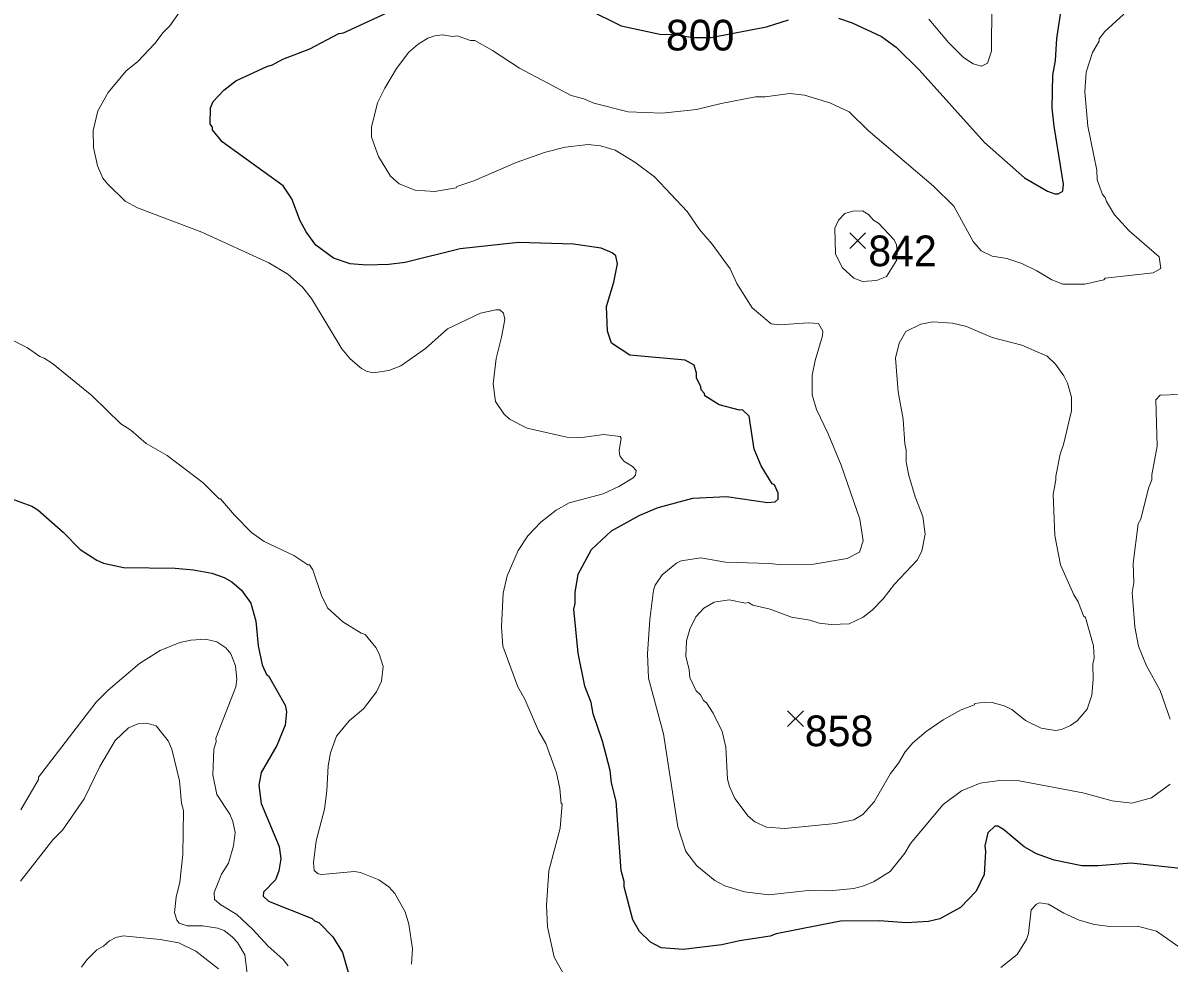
# Model space of a CAD drawing. Extents: x 265.7 to 292.1, y 7676.2 to 7704.2.
# Drawn here: x 270.421 to 273.408, y 7689.995 to 7692.446 of the extents above; entities that cross this region are included whole.
import ezdxf
from ezdxf.enums import TextEntityAlignment as Align

# ---------------------------------------------------------------- set-up
doc = ezdxf.new("R2010")
doc.units = 0
doc.header["$LTSCALE"] = 0.032
for name, color, linetype, lineweight in [('1', 7, 'Continuous', 25), ('2', 7, 'Continuous', 13), ('21', 7, 'Continuous', 25)]:
    doc.layers.add(name, color=color, linetype=linetype, lineweight=lineweight)
doc.layers.add('61', color=7, linetype='Continuous')

msp = doc.modelspace()

# ---------------------------------------------------------------- linework, layer by layer
at = {"layer": '1'}
for points in [[(271.4171, 7691.8211), (271.374, 7691.8163), (271.3166, 7691.8147), (271.2735, 7691.8179), (271.2304, 7691.8323), (271.1841, 7691.8666), (271.1586, 7691.9009), (271.1434, 7691.9296), (271.1219, 7691.9871), (271.0987, 7692.0214), (270.9399, 7692.1355), (270.9144, 7692.1674), (270.9144, 7692.1738), (270.9088, 7692.1818), (270.9096, 7692.2249), (270.9168, 7692.2409), (270.9439, 7692.2704), (270.9758, 7692.2951), (271.0564, 7692.3326), (271.0708, 7692.3366), (271.0979, 7692.3518), (271.1682, 7692.3781), (271.244, 7692.418), (271.2559, 7692.4204), (271.4123, 7692.4922)], [(271.8927, 7692.4818), (271.9805, 7692.4387), (272.081, 7692.4164), (272.1199, 7692.4156), (272.1671, 7692.4081), (272.2142, 7692.4081), (272.3587, 7692.4355), (272.4162, 7692.4539)], [(272.547, 7692.4587), (272.5821, 7692.4459), (272.6587, 7692.4108), (272.697, 7692.3829), (272.7569, 7692.3238), (272.9276, 7692.1339), (273.0314, 7692.0422), (273.0912, 7692.007), (273.1104, 7691.9999), (273.1192, 7691.9999), (273.1311, 7692.007), (273.1335, 7692.0254), (273.1088, 7692.177), (273.104, 7692.2233), (273.1056, 7692.3095), (273.112, 7692.3478), (273.116, 7692.4052), (273.1295, 7692.4962)], [(271.9661, 7691.8387), (271.9565, 7691.8467), (271.9278, 7691.8586), (271.856, 7691.869), (271.7124, 7691.8738), (271.5608, 7691.857), (271.4171, 7691.8211)], [(273.4535, 7690.2395), (273.3099, 7690.2555), (273.2237, 7690.2483), (273.1806, 7690.2483), (273.1088, 7690.2627), (273.0625, 7690.2794), (273.0306, 7690.2978), (272.9771, 7690.3433), (272.962, 7690.3513), (272.954, 7690.3513), (272.9356, 7690.3345), (272.9284, 7690.3002), (272.93, 7690.2858), (272.926, 7690.2252), (272.9053, 7690.1821), (272.8646, 7690.1398), (272.8104, 7690.1103), (272.7816, 7690.1031), (272.7242, 7690.0999), (272.6524, 7690.1047), (272.5518, 7690.1039), (272.3842, 7690.0712), (272.3683, 7690.0648), (272.2885, 7690.0528), (272.2422, 7690.0425), (272.1417, 7690.0297), (272.0842, 7690.0345), (272.0563, 7690.0488), (272.0283, 7690.0768), (272.0108, 7690.1071), (271.9877, 7690.1933), (271.9877, 7690.2076), (271.9805, 7690.2364), (271.9669, 7690.4167), (271.9549, 7690.4646), (271.9517, 7690.4965), (271.931, 7690.5731), (271.9071, 7690.6449), (271.9015, 7690.6737), (271.8855, 7690.7167), (271.868, 7690.8029), (271.8568, 7690.9178), (271.86, 7690.9322), (271.86, 7690.9609), (271.868, 7691.0088), (271.9031, 7691.0726), (271.9549, 7691.1213), (272.0284, 7691.1628), (272.0762, 7691.1827), (272.1672, 7691.2067), (272.255, 7691.2107), (272.3619, 7691.1955), (272.3819, 7691.1971), (272.3898, 7691.2043), (272.389, 7691.2195), (272.3794, 7691.2418), (272.3739, 7691.2442), (272.3451, 7691.2913), (272.3268, 7691.3344), (272.314, 7691.4205), (272.2965, 7691.4373), (272.2885, 7691.4365), (272.2358, 7691.4501), (272.1983, 7691.4732), (272.1975, 7691.4796), (272.1887, 7691.4892), (272.1879, 7691.4971), (272.1768, 7691.5203), (272.1768, 7691.5323), (272.1704, 7691.5538), (272.1465, 7691.5666), (272.0028, 7691.5793), (271.9549, 7691.6113), (271.9446, 7691.6424), (271.9422, 7691.7062), (271.9613, 7691.7701), (271.9701, 7691.8179), (271.9661, 7691.8387)], [(270.3957, 7691.2035), (270.4436, 7691.1859), (270.4596, 7691.1764), (270.5258, 7691.1181), (270.5697, 7691.0726), (270.6128, 7691.0447), (270.6303, 7691.0375), (270.683, 7691.0263), (270.8171, 7691.0247), (270.8649, 7691.02), (270.9128, 7691.0112), (270.9447, 7691), (270.9655, 7690.9888), (270.9902, 7690.9673), (271.0149, 7690.933), (271.0277, 7690.8859), (271.0341, 7690.8221), (271.0445, 7690.7726), (271.0556, 7690.7471), (271.0604, 7690.7439), (271.1043, 7690.6673), (271.1075, 7690.6497), (271.1043, 7690.6146), (271.082, 7690.5619), (271.0413, 7690.4917), (271.0357, 7690.4582), (271.0413, 7690.4103), (271.0883, 7690.2986), (271.0931, 7690.2667), (271.0875, 7690.2348), (271.0788, 7690.2116), (271.0476, 7690.1797), (271.0469, 7690.1693), (271.0604, 7690.1558), (271.1745, 7690.1111), (271.1809, 7690.1047), (271.1921, 7690.1007), (271.228, 7690.0632), (271.2535, 7690.0225), (271.2791, 7689.9347)]]:
    msp.add_lwpolyline(points, dxfattribs=at)
at = {"layer": '2'}
for points in [[(270.841, 7692.4914), (270.8035, 7692.4387), (270.7859, 7692.4212), (270.7644, 7692.3925), (270.7189, 7692.3446), (270.6894, 7692.3206), (270.6431, 7692.2648), (270.616, 7692.2169), (270.604, 7692.1658), (270.6048, 7692.1212), (270.6152, 7692.0733), (270.6287, 7692.0414), (270.6407, 7692.0262), (270.687, 7691.9815), (270.7189, 7691.964), (270.8873, 7691.9001), (271.0612, 7691.8203), (271.1115, 7691.7908), (271.149, 7691.7565), (271.1729, 7691.727), (271.2519, 7691.5961), (271.2735, 7691.5698), (271.303, 7691.545), (271.3182, 7691.537), (271.3341, 7691.5338), (271.374, 7691.5394), (271.4059, 7691.5522), (271.4698, 7691.5969), (271.5272, 7691.648), (271.6134, 7691.6895), (271.6533, 7691.6982), (271.6637, 7691.6974), (271.6733, 7691.6887), (271.6765, 7691.6727), (271.6685, 7691.6264), (271.6541, 7691.5706), (271.6461, 7691.5051), (271.6525, 7691.4588), (271.6741, 7691.4269), (271.6892, 7691.4126), (271.7347, 7691.3894), (271.8384, 7691.3655), (271.8783, 7691.3647), (271.9342, 7691.3727), (271.9773, 7691.3679), (271.9797, 7691.3631), (271.9749, 7691.3312), (271.9765, 7691.3168), (271.9869, 7691.3032), (272.0092, 7691.2897)], [(272.9468, 7692.493), (272.9452, 7692.3725), (272.9348, 7692.3406), (272.9197, 7692.3334), (272.8973, 7692.339), (272.8726, 7692.3558), (272.8343, 7692.3941), (272.7824, 7692.4555)], [(273.2907, 7692.4691), (273.2413, 7692.4236), (273.2261, 7692.4044), (273.2261, 7692.398), (273.2085, 7692.3685), (273.1926, 7692.3175), (273.1886, 7692.2664), (273.1966, 7692.177), (273.2197, 7692.0621), (273.2213, 7692.0366)], [(273.3825, 7691.8363), (273.3873, 7691.806), (273.3673, 7691.794), (273.2421, 7691.7804), (273.2381, 7691.7764), (273.1886, 7691.7645), (273.1311, 7691.7645), (273.1024, 7691.7764), (273.0641, 7691.7996), (273.0242, 7691.8187), (272.9859, 7691.8315), (272.9476, 7691.8379), (272.9189, 7691.8514), (272.8973, 7691.8762), (272.8471, 7691.9679), (272.7944, 7692.0206), (272.6236, 7692.1658), (272.5742, 7692.2137), (272.5239, 7692.2377), (272.4577, 7692.2576), (272.4194, 7692.2616), (272.3555, 7692.2528), (272.33, 7692.2528), (272.2406, 7692.2361), (272.1768, 7692.2201), (272.0874, 7692.2105), (271.998, 7692.2137), (271.9087, 7692.2369), (271.8831, 7692.248), (271.8496, 7692.2568), (271.7148, 7692.3278), (271.6445, 7692.3741), (271.5983, 7692.4004), (271.5871, 7692.4004), (271.5528, 7692.4124), (271.54, 7692.4108), (271.5145, 7692.4148), (271.4945, 7692.4124), (271.4762, 7692.406), (271.4506, 7692.3909), (271.4267, 7692.3693), (271.3948, 7692.327), (271.3636, 7692.276), (271.3445, 7692.2377), (271.3293, 7692.1738), (271.3293, 7692.1483), (271.3477, 7692.0972), (271.3788, 7692.0461), (271.4012, 7692.0262), (271.4427, 7692.0102), (271.4937, 7692.0062), (271.5496, 7692.0158), (271.552, 7692.019), (271.5959, 7692.0342), (271.706, 7692.0821), (271.7826, 7692.1092), (271.8337, 7692.1219), (271.8943, 7692.1291), (271.9262, 7692.1251), (271.9645, 7692.114), (272.0156, 7692.0828), (272.0667, 7692.0445), (272.152, 7691.9544), (272.1847, 7691.9073), (272.2175, 7691.869), (272.2646, 7691.8044), (272.2813, 7691.7669), (272.3212, 7691.703), (272.3715, 7691.6615), (272.3922, 7691.6591), (272.4688, 7691.6639), (272.4944, 7691.6623), (272.5055, 7691.6424), (272.5047, 7691.6296), (272.4856, 7691.5658), (272.4776, 7691.5275), (272.4776, 7691.4764), (272.4896, 7691.4381), (272.5199, 7691.3743), (272.5534, 7691.2929), (272.6021, 7691.1524), (272.6109, 7691.0958), (272.6013, 7691.0662), (272.5694, 7691.0495), (272.4816, 7691.0351), (272.3922, 7691.0335), (272.3667, 7691.0367), (272.2518, 7691.0399), (272.1879, 7691.0511), (272.1369, 7691.0431), (272.1241, 7691.0375), (272.0866, 7691.0072), (272.069, 7690.9801), (272.0643, 7690.9673), (272.0547, 7690.8907)], [(273.2213, 7692.0366), (273.2349, 7691.9983), (273.2421, 7691.9911), (273.2452, 7691.9807), (273.266, 7691.9456), (273.3043, 7691.9041), (273.3825, 7691.8363)], [(273.1105, 7691.1096), (273.1255, 7691.0327), (273.1599, 7690.9545), (273.1718, 7690.9362), (273.1854, 7690.9003), (273.1902, 7690.8955), (273.2117, 7690.8221), (273.2133, 7690.7902), (273.2101, 7690.7742), (273.2109, 7690.7343), (273.2069, 7690.6928), (273.195, 7690.6569), (273.1686, 7690.6258), (273.1519, 7690.6138), (273.1279, 7690.6034), (273.112, 7690.601), (273.0753, 7690.6074), (273.0338, 7690.6274), (272.9987, 7690.6561), (272.9787, 7690.6657), (272.9476, 7690.6744), (272.9285, 7690.6752), (272.9021, 7690.6713), (272.9013, 7690.6681), (272.8662, 7690.6553), (272.8199, 7690.629), (272.7752, 7690.5986), (272.7401, 7690.5691), (272.7202, 7690.5452), (272.7034, 7690.5157), (272.6819, 7690.4885), (272.6396, 7690.4151), (272.6101, 7690.3824), (272.5869, 7690.368), (272.5391, 7690.3585), (272.4066, 7690.3457), (272.3587, 7690.3489), (272.3284, 7690.3632), (272.3108, 7690.3776), (272.2765, 7690.4239), (272.2622, 7690.455), (272.2574, 7690.4742), (272.2526, 7690.5572), (272.243, 7690.5986), (272.2199, 7690.6465), (272.2023, 7690.6728), (272.1943, 7690.6792), (272.1871, 7690.6936), (272.1752, 7690.7048), (272.1592, 7690.7391), (272.1576, 7690.759), (272.1488, 7690.7949), (272.1504, 7690.8348), (272.1592, 7690.8652), (272.1744, 7690.8971), (272.1959, 7690.9202), (272.2223, 7690.9354), (272.2614, 7690.9418), (272.3045, 7690.933), (272.3116, 7690.9346), (272.3236, 7690.9282), (272.3683, 7690.917), (272.4241, 7690.8963), (272.472, 7690.8883), (272.496, 7690.8811), (272.5279, 7690.8771), (272.5742, 7690.8795), (272.6109, 7690.8963), (272.6348, 7690.9146), (272.6635, 7690.9442), (272.6923, 7690.9825), (272.7521, 7691.0447), (272.7641, 7691.0686), (272.7728, 7691.1125), (272.7665, 7691.1588), (272.7465, 7691.2099), (272.7298, 7691.2657), (272.7234, 7691.3008), (272.7234, 7691.3328), (272.7194, 7691.3487), (272.7154, 7691.4126), (272.7026, 7691.4844), (272.6954, 7691.5722), (272.705, 7691.6105), (272.7226, 7691.6416), (272.7609, 7691.6607), (272.7928, 7691.6663), (272.8439, 7691.6631), (272.8806, 7691.6543), (272.9476, 7691.6256), (273.0242, 7691.6057), (273.0904, 7691.5769), (273.112, 7691.5562), (273.1343, 7691.5259), (273.1439, 7691.5067)], [(271.4339, 7689.9922), (271.4363, 7690.0321), (271.4267, 7690.0959), (271.4171, 7690.1278), (271.39, 7690.1757), (271.3748, 7690.1933), (271.3485, 7690.2116), (271.3006, 7690.2308), (271.2847, 7690.2332), (271.2001, 7690.2252), (271.1905, 7690.2276), (271.1801, 7690.2364), (271.1777, 7690.2571), (271.1849, 7690.313), (271.2064, 7690.396), (271.2128, 7690.4438), (271.216, 7690.5093), (271.2224, 7690.5428), (271.2384, 7690.5859), (271.2711, 7690.6258), (271.3086, 7690.6577), (271.3421, 7690.7016), (271.3557, 7690.7295), (271.3597, 7690.7678), (271.3493, 7690.8013), (271.3405, 7690.8173), (271.3126, 7690.8516), (271.3022, 7690.8548), (271.2543, 7690.8843), (271.2144, 7690.921), (271.1993, 7690.9529), (271.1761, 7691.02), (271.1674, 7691.0327), (271.1634, 7691.0327), (271.1267, 7691.0575), (271.0493, 7691.0942), (271.0165, 7691.1173), (270.9719, 7691.1628), (270.9359, 7691.2051), (270.932, 7691.2051), (270.8905, 7691.2466), (270.7963, 7691.3184), (270.742, 7691.3495), (270.7021, 7691.3838), (270.6758, 7691.4006), (270.6008, 7691.474), (270.4979, 7691.5578), (270.4763, 7691.5722), (270.4644, 7691.5761), (270.4324, 7691.5985), (270.383, 7691.624)], [(273.1439, 7691.5067), (273.1543, 7691.47), (273.1543, 7691.4349), (273.1335, 7691.3471), (273.1247, 7691.3216), (273.1128, 7691.2641), (273.1136, 7691.2546)], [(273.4112, 7690.6306), (273.3849, 7690.7056), (273.3498, 7690.7694), (273.329, 7690.8205), (273.3195, 7690.8715), (273.3123, 7690.9609), (273.3163, 7690.9865), (273.3147, 7691.0375), (273.3282, 7691.1397), (273.3346, 7691.1524), (273.3546, 7691.233), (273.3633, 7691.2546), (273.3633, 7691.2673), (273.3777, 7691.3423), (273.3737, 7691.4628), (273.3849, 7691.4756), (273.4344, 7691.4772)], [(272.0092, 7691.2897), (272.0188, 7691.2793), (272.0172, 7691.2665), (272.0116, 7691.2601), (271.9741, 7691.237), (271.9334, 7691.2179), (271.8448, 7691.1947)], [(273.1136, 7691.2546), (273.1064, 7691.2163), (273.1105, 7691.1096)], [(271.8448, 7691.1947), (271.8105, 7691.1756), (271.7706, 7691.1444), (271.7371, 7691.1085), (271.7116, 7691.0702), (271.6828, 7691.004), (271.6725, 7690.9593), (271.6685, 7690.8715), (271.6717, 7690.8205), (271.7108, 7690.7151), (271.7291, 7690.6824), (271.7642, 7690.6002), (271.7834, 7690.5667), (271.8113, 7690.4909), (271.8201, 7690.4502), (271.8241, 7690.4095), (271.8265, 7690.4095), (271.8209, 7690.3465), (271.7914, 7690.2348), (271.7858, 7690.1454), (271.7882, 7690.0887), (271.8057, 7690.0097), (271.8336, 7689.9603)], [(272.0547, 7690.8907), (272.0483, 7690.8013), (272.0515, 7690.7375), (272.0906, 7690.5923), (272.1281, 7690.3497), (272.1488, 7690.2858), (272.1776, 7690.2483)], [(271.1123, 7689.9874), (271.0987, 7690.0042), (271.0596, 7690.0385), (271.0197, 7690.0824), (270.9782, 7690.1215), (270.9367, 7690.1462), (270.92, 7690.1606), (270.9192, 7690.1789), (270.9383, 7690.2268), (270.9567, 7690.2555), (270.9695, 7690.3002), (270.9734, 7690.3353), (270.9679, 7690.364), (270.9599, 7690.3832), (270.9264, 7690.4343), (270.9152, 7690.4853), (270.9184, 7690.5524), (270.924, 7690.5715), (270.9232, 7690.5811), (270.9758, 7690.7151), (270.9782, 7690.7343), (270.975, 7690.7694), (270.9623, 7690.8013), (270.9495, 7690.8165), (270.9264, 7690.8324), (270.8968, 7690.8388), (270.8585, 7690.8364), (270.8298, 7690.8308), (270.7787, 7690.8093), (270.7245, 7690.7758), (270.6423, 7690.7064), (270.6112, 7690.6752), (270.4612, 7690.4797), (270.4612, 7690.4734), (270.4149, 7690.3944)], [(271.0054, 7689.9683), (270.999, 7690.0161), (270.9798, 7690.0481), (270.9663, 7690.0632), (270.9447, 7690.0792), (270.9288, 7690.0856), (270.8889, 7690.0919), (270.849, 7690.0919), (270.8282, 7690.0983), (270.8218, 7690.1063), (270.8155, 7690.1263), (270.8202, 7690.1662), (270.8298, 7690.206), (270.8378, 7690.2779), (270.8394, 7690.3928), (270.8338, 7690.4119), (270.829, 7690.4694), (270.8091, 7690.5524), (270.7995, 7690.5739), (270.7676, 7690.613), (270.7436, 7690.6202), (270.7197, 7690.6186), (270.6958, 7690.6082), (270.6606, 7690.5747), (270.6207, 7690.5069), (270.5801, 7690.4231), (270.5234, 7690.3409), (270.4987, 7690.3162), (270.4141, 7690.2084)], [(272.1776, 7690.2483), (272.2247, 7690.21), (272.2502, 7690.1957), (272.3013, 7690.1805), (272.3651, 7690.1725), (272.4672, 7690.1837), (272.5231, 7690.1829), (272.5869, 7690.1893), (272.6125, 7690.1957), (272.638, 7690.2068), (272.6811, 7690.2332), (272.7194, 7690.2811), (272.7345, 7690.3066), (272.8191, 7690.4079), (272.867, 7690.4438), (272.9157, 7690.4638), (272.9668, 7690.471), (273.0178, 7690.4702), (273.1838, 7690.4382), (273.2604, 7690.4175), (273.3115, 7690.4119), (273.3625, 7690.4255), (273.4112, 7690.4614)], [(272.9699, 7689.9834), (273.0122, 7690.0169), (273.037, 7690.056), (273.0418, 7690.072), (273.0489, 7690.1334), (273.0625, 7690.1486), (273.0705, 7690.1518), (273.0944, 7690.1478), (273.1343, 7690.1246), (273.1742, 7690.1063), (273.2141, 7690.0951), (273.254, 7690.0903), (273.3258, 7690.0911), (273.3753, 7690.0776), (273.4423, 7690.0313)], [(270.5729, 7689.9842), (270.5872, 7690.0034), (270.6136, 7690.0289), (270.6303, 7690.0385), (270.6463, 7690.0528), (270.663, 7690.0616), (270.6814, 7690.0656), (270.7787, 7690.056), (270.8266, 7690.0472), (270.8715, 7690.0256), (270.9304, 7689.9794)]]:
    msp.add_lwpolyline(points, dxfattribs=at)
msp.add_lwpolyline([(272.6911, 7691.8811), (272.6977, 7691.8678), (272.6997, 7691.8466), (272.6977, 7691.8267), (272.6715, 7691.7844), (272.646, 7691.774), (272.6093, 7691.7716), (272.5869, 7691.7804), (272.5558, 7691.8084), (272.539, 7691.8435), (272.5374, 7691.9105), (272.547, 7691.9312), (272.563, 7691.9488), (272.5837, 7691.9552), (272.6093, 7691.956), (272.6252, 7691.9464), (272.638, 7691.932), (272.6508, 7691.9241)], close=True, dxfattribs=at)
at = {"layer": '21'}
for p, q in [((272.5761, 7691.8987), (272.6173, 7691.8575)), ((272.6173, 7691.8987), (272.5761, 7691.8575)), ((272.4138, 7690.6526), (272.455, 7690.6114)), ((272.455, 7690.6526), (272.4138, 7690.6114))]:
    msp.add_line(p, q, dxfattribs=at)

# ---------------------------------------------------------------- texts
at = {"layer": '61'}
for s, p in [('800', (272.1861, 7692.3741)), ('842', (272.7136, 7691.8116)), ('858', (272.5482, 7690.5601))]:
    msp.add_text(s, height=0.08, dxfattribs=at).set_placement(p, align=Align.CENTER)

doc.saveas('drawing.dxf')
